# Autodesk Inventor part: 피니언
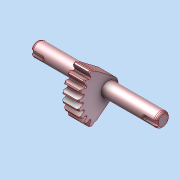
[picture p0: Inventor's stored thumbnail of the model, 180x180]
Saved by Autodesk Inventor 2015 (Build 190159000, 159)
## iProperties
Created: 2024-06
Part Number: 피니언
Material: 일반
Document SubType Name: Modeling
Designer: Administrator
Density: 1 g/cm^3
Appearance: 기본값
Author: Administrator
Author: jhkim
Creation Date: 2024-05-29
Sending System: Autodesk Inventor 2025
Preprocessor: ST-DEVELOPER v20
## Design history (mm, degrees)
node "피니언1"
node "솔리드1"
node "기준1"
